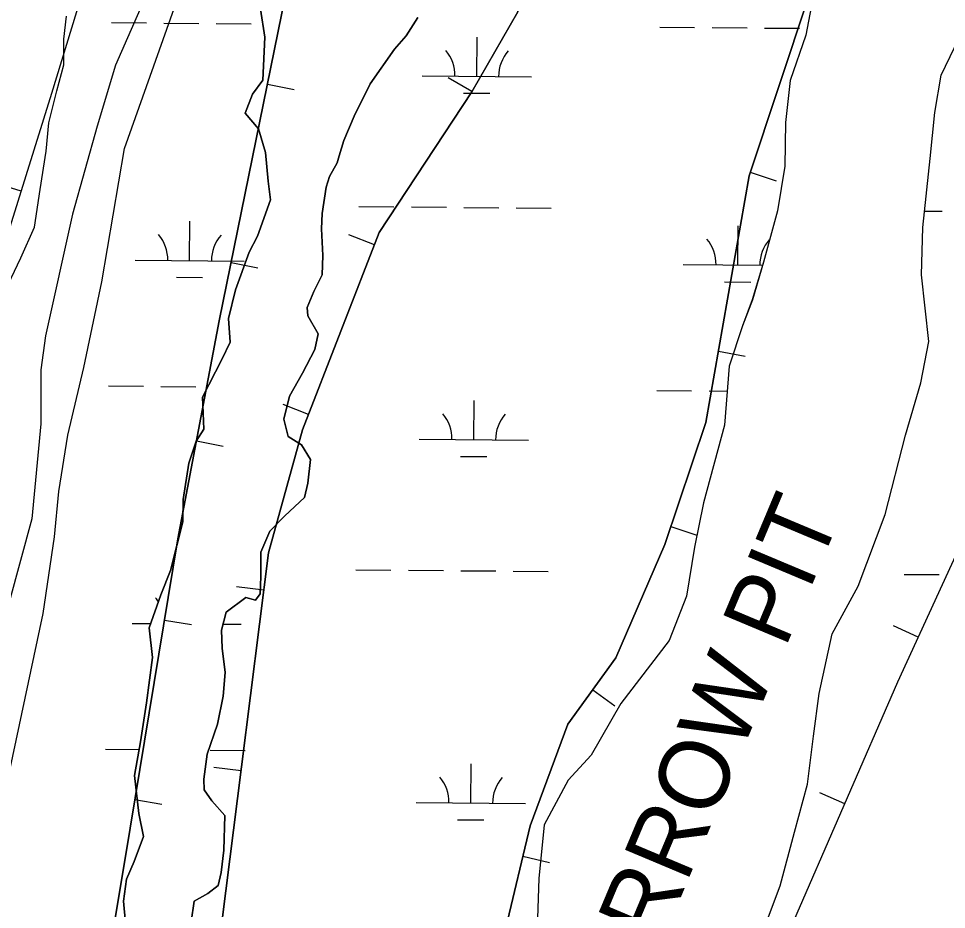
# Model space of a CAD drawing. Extents: x 3271442 to 3309282, y 752266 to 777610.
# Drawn here: x 3287641 to 3288490, y 773012 to 773828 of the extents above; entities that cross this region are included whole.
import ezdxf

# ---------------------------------------------------------------- set-up
doc = ezdxf.new("R2010")
doc.units = 0
for name, color, linetype in [('V-BORW-IDEN', 7, 'Continuous'), ('V-BORW-LINE', 7, 'Continuous'), ('V-SITE-VEGE', 7, 'Continuous'), ('V-TOPO-SHOR', 7, 'Continuous'), ('V-WETL-SWMP', 7, 'Continuous')]:
    doc.layers.add(name, color=color, linetype=linetype)

msp = doc.modelspace()

# ---------------------------------------------------------------- linework, layer by layer
at = {"layer": 'V-BORW-LINE'}
for p, q in [((3288056.11, 773761.26), (3288034.44, 773773.71)), ((3287868.85, 773768.1), (3287893.34, 773763.11)), ((3288310.88, 773687.36), (3288334.62, 773679.5)), ((3287643.36, 773669.95), (3287619.48, 773677.36)), ((3287966.74, 773620.96), (3287943.43, 773630)), ((3287835.59, 773604.85), (3287860.08, 773599.86)), ((3288281.68, 773523.38), (3288306.3, 773519.08)), ((3287906.5, 773465.63), (3287883.19, 773474.67)), ((3287803.8, 773441.32), (3287828.36, 773436.65)), ((3288238.19, 773363.04), (3288261.88, 773355.05)), ((3287865.43, 773304.59), (3287840.62, 773307.7)), ((3287774.59, 773277.31), (3287799.26, 773273.26)), ((3288464.55, 773261.51), (3288441.83, 773271.94)), ((3288166.6, 773213.49), (3288186.84, 773198.83)), ((3287844.66, 773139.29), (3287819.85, 773142.42)), ((3288397.31, 773109.09), (3288374.38, 773119.05)), ((3287747.62, 773112.91), (3287772.3, 773108.86)), ((3288102.7, 773061.24), (3288127.02, 773055.45))]:
    msp.add_line(p, q, dxfattribs=at)
for points in [[(3287960.94, 771424.94), (3288014.47, 771603.18), (3288066.68, 771823.14), (3288098.99, 772040.91), (3288128.22, 772249.7), (3288166.71, 772489.22), (3288222.94, 772713.67), (3288347.64, 772994.79), (3288445.81, 773220.69), (3288556.67, 773462.19), (3288616.39, 773637.62), (3288621.98, 773818.51), (3288618.9, 774004.11), (3288683.35, 774231.23), (3288776.13, 774650.85), (3288910.27, 775079.52), (3289045.78, 775496.93), (3289097.91, 775727.38), (3289093.15, 775796.21), (3289077.54, 775831.36)], [(3287946.02, 772379.82), (3287909.12, 772439.3), (3287896.09, 772502.81), (3287913.88, 772541.62), (3287925.45, 772619.81), (3287948.76, 772734.43), (3288021.53, 772853.96), (3288087.08, 772995.64), (3288109.28, 773088.9), (3288143.83, 773182.06), (3288187.85, 773242.85), (3288232.59, 773346.45), (3288270.29, 773458.26), (3288309.76, 773683.96), (3288364.37, 773848.74), (3288384.32, 773880.81), (3288422.6, 773916.87), (3288452.86, 774014.74), (3288459.7, 774112.63), (3288521, 774269.88)], [(3288521, 774269.88), (3288459.7, 774112.63), (3288452.86, 774014.74), (3288422.6, 773916.87), (3288384.32, 773880.81), (3288364.37, 773848.74), (3288309.76, 773683.96), (3288270.29, 773458.26), (3288232.59, 773346.45), (3288187.85, 773242.85), (3288143.83, 773182.06), (3288109.28, 773088.9), (3288087.08, 772995.64), (3288021.53, 772853.96), (3287948.76, 772734.43), (3287925.45, 772619.81), (3287913.88, 772541.62), (3287896.09, 772502.81), (3287909.12, 772439.3), (3287946.02, 772379.82)], [(3287874.44, 774249.61), (3287801.65, 774123.05), (3287726.03, 773939.09), (3287671.15, 773759.54), (3287624.33, 773608.59), (3287591.03, 773444.42), (3287559.74, 773238.91), (3287539.14, 773034.75), (3287545.26, 772863.66), (3287544.82, 772819.24), (3287514.6, 772720.21), (3287469.36, 772546.13), (3287459.15, 772437.07), (3287443.04, 772332.46)], [(3287885.48, 773849.72), (3287945.3, 773921.21), (3288015.71, 774031.69), (3288090.25, 774050.35), (3288124.87, 773978.23), (3288098.03, 773834.21), (3288055.98, 773761.02), (3287971.03, 773632.03), (3287900.96, 773451.34), (3287869.74, 773338.91), (3287845.1, 773142.82), (3287827.09, 773000.32), (3287812.48, 772836.24), (3287772.24, 772685.02), (3287706.68, 772579.32), (3287664.96, 772582.37), (3287662.79, 772664.89), (3287700.72, 772832.42), (3287739.07, 773060.74), (3287786.79, 773351.73), (3287824.7, 773551.43), (3287885.48, 773849.72)], [(3287885.48, 773849.72), (3287824.7, 773551.43), (3287786.79, 773351.73), (3287739.07, 773060.74), (3287700.72, 772832.42), (3287662.79, 772664.89), (3287664.96, 772582.37), (3287706.68, 772579.32), (3287772.24, 772685.02), (3287812.48, 772836.24), (3287827.09, 773000.32), (3287845.1, 773142.82), (3287869.74, 773338.91), (3287900.96, 773451.34), (3287971.03, 773632.03), (3288055.98, 773761.02), (3288098.03, 773834.21), (3288124.87, 773978.23), (3288090.25, 774050.35), (3288015.71, 774031.69), (3287944.3, 773945.08), (3287885.48, 773849.72)]]:
    msp.add_lwpolyline(points, dxfattribs=at)
at = {"layer": 'V-SITE-VEGE'}
for points in [[(3287630.5, 773128.36), (3287663.55, 773283.32), (3287673.87, 773353.57), (3287678, 773394.89), (3287686.27, 773446.54), (3287700.72, 773508.53), (3287717.24, 773587.04), (3287737.9, 773708.94), (3287793.66, 773865.96), (3287797.79, 773905.22), (3287812.25, 773940.34), (3287832.9, 773973.4), (3287863.88, 774029.19), (3287892.79, 774082.91), (3287923.77, 774120.1), (3287954.75, 774146.96), (3287993.99, 774163.49), (3288027.03, 774159.35), (3288066.27, 774144.89), (3288140.62, 774105.64), (3288188.12, 774082.91), (3288214.97, 774068.44), (3288243.01, 774030.1)], [(3287775.07, 773888.69), (3287729.63, 773785.39), (3287713.11, 773729.6), (3287690.4, 773649.02), (3287665.61, 773537.45), (3287661.48, 773506.46), (3287661.48, 773456.87), (3287653.22, 773370.1), (3287632.57, 773293.65)], [(3288367.66, 773845.12), (3288361.68, 773812.93), (3288347.46, 773771.39), (3288343.21, 773732.75), (3288342.48, 773692.93), (3288335.88, 773651.95), (3288322.81, 773605.14), (3288312.73, 773570.62), (3288303.85, 773546.64), (3288291.41, 773509.79), (3288287.1, 773455.91), (3288268.09, 773384.53), (3288259.73, 773344.15), (3288252.53, 773299.07), (3288236.57, 773258.72), (3288192.42, 773200.9), (3288165.29, 773153.56), (3288144.12, 773130.79), (3288122.29, 773089.87), (3288117.42, 773040.69), (3288116.11, 773004.38)], [(3287862.4, 773836.71), (3287866.41, 773810.92), (3287864.5, 773771.69), (3287855.08, 773758.84), (3287848.57, 773741.29), (3287860.81, 773727.18), (3287867.18, 773705.49), (3287869.42, 773679.12), (3287871.7, 773662.12), (3287859.85, 773628.78), (3287852.19, 773614.17), (3287839.75, 773579.66), (3287833.21, 773553.33), (3287834.89, 773531.65), (3287827.21, 773515.86), (3287809.51, 773481.37), (3287810.57, 773452.08), (3287803.5, 773440.98), (3287796.98, 773421.09), (3287791.58, 773387.72), (3287791.5, 773367.22), (3287780.2, 773322.75), (3287771.33, 773300.53), (3287760.67, 773270.11), (3287763.5, 773243.15), (3287758.07, 773201.59), (3287752.66, 773165.88), (3287747.27, 773134.86), (3287751.24, 773100.28), (3287755.26, 773079.18), (3287746.98, 773056.37), (3287739.89, 773039.99), (3287737.22, 773019.78)], [(3287628.39, 773578), (3287643.15, 773608.99), (3287655.55, 773637.06), (3287660.96, 773671.59), (3287666.36, 773706.72), (3287668.8, 773732.48), (3287675.94, 773761.74), (3287682.48, 773785.73), (3287682.56, 773809.16), (3287684.99, 773830.23)], [(3287985.27, 773799.93), (3287995.86, 773812.19), (3288006.47, 773829.13)], [(3287798.9, 773001.11), (3287801.89, 773019.84), (3287814.22, 773026.83), (3287823.62, 773034.41), (3287826.6, 773046.11), (3287829.02, 773066.6), (3287829.72, 773098.23), (3287818.06, 773111.74), (3287811.07, 773121.73), (3287810.52, 773131.69), (3287813.54, 773154.52), (3287823.01, 773182.01), (3287828.38, 773207.76), (3287830.22, 773229.43), (3287827.38, 773251.7), (3287826.86, 773268.1), (3287831.02, 773284.48), (3287849.23, 773297.89), (3287858, 773295.51), (3287862.12, 773301.35), (3287862.77, 773317.16), (3287862.85, 773339.42), (3287871.13, 773358.72), (3287884.65, 773372.72), (3287902.88, 773389.65), (3287905.85, 773402.52), (3287908.28, 773424.18), (3287900.13, 773437.69), (3287887.86, 773445.34), (3287883.82, 773461.17), (3287889.17, 773482.24), (3287900.97, 773503.28), (3287912.18, 773524.91), (3287915.16, 773539.54), (3287905.85, 773555.98), (3287905.29, 773563.6), (3287911.21, 773578.22), (3287918.88, 773593.42), (3287919.53, 773610.98), (3287918.45, 773635.59), (3287919.09, 773649.65), (3287922.7, 773673.65), (3287925.67, 773683.59), (3287932.74, 773695.87), (3287934.52, 773702.3), (3287938.68, 773716.34), (3287948.13, 773738.57), (3287962.89, 773768.38), (3287985.27, 773799.93)], [(3287737.22, 773019.78), (3287738.86, 773000.14)]]:
    msp.add_lwpolyline(points, dxfattribs=at)
at = {"layer": 'V-TOPO-SHOR'}
for points in [[(3288367.66, 773845.12), (3288361.68, 773812.93), (3288347.46, 773771.39), (3288343.21, 773732.75), (3288342.48, 773692.93), (3288335.88, 773651.95), (3288322.81, 773605.14), (3288312.73, 773570.62), (3288303.85, 773546.64), (3288291.41, 773509.79), (3288287.1, 773455.91), (3288268.09, 773384.53), (3288259.73, 773344.15), (3288252.53, 773299.07), (3288236.57, 773258.72), (3288192.42, 773200.9), (3288165.29, 773153.56), (3288144.12, 773130.79), (3288122.29, 773089.87), (3288117.42, 773040.69), (3288116.11, 773004.38)], [(3287737.21, 773019.78), (3287739.89, 773039.99), (3287746.98, 773056.37), (3287755.26, 773079.18), (3287751.24, 773100.28), (3287747.27, 773134.85), (3287752.66, 773165.88), (3287758.07, 773201.59), (3287763.5, 773243.15), (3287760.67, 773270.11), (3287771.33, 773300.53), (3287780.2, 773322.75), (3287791.5, 773367.22), (3287791.58, 773387.72), (3287796.98, 773421.09), (3287803.5, 773440.98), (3287810.57, 773452.08), (3287809.51, 773481.37), (3287827.21, 773515.86), (3287834.89, 773531.65), (3287833.21, 773553.33), (3287839.75, 773579.66), (3287852.19, 773614.17), (3287859.85, 773628.78), (3287871.7, 773662.12), (3287869.42, 773679.12), (3287867.18, 773705.49), (3287860.81, 773727.18), (3287848.57, 773741.29), (3287855.08, 773758.84), (3287864.5, 773771.69), (3287866.41, 773810.92), (3287862.4, 773836.71)], [(3288006.46, 773829.13), (3287995.86, 773812.19), (3287985.27, 773799.93), (3287962.89, 773768.38), (3287948.13, 773738.57), (3287938.68, 773716.34), (3287934.52, 773702.3), (3287932.74, 773695.87), (3287925.67, 773683.59), (3287922.7, 773673.65), (3287919.09, 773649.65), (3287918.45, 773635.59), (3287919.53, 773610.98), (3287918.88, 773593.42), (3287911.21, 773578.22), (3287905.29, 773563.6), (3287905.85, 773555.98), (3287915.16, 773539.54), (3287912.18, 773524.91), (3287900.97, 773503.28), (3287889.17, 773482.24), (3287883.82, 773461.17), (3287887.86, 773445.34), (3287900.13, 773437.68), (3287908.28, 773424.18), (3287905.85, 773402.52), (3287902.88, 773389.64), (3287884.65, 773372.72), (3287871.13, 773358.72), (3287862.85, 773339.42), (3287862.77, 773317.16), (3287862.12, 773301.35), (3287858, 773295.51), (3287849.23, 773297.89), (3287831.02, 773284.48), (3287826.85, 773268.1), (3287827.38, 773251.7), (3287830.22, 773229.43)], [(3287830.22, 773229.43), (3287828.38, 773207.76), (3287823.01, 773182.01), (3287813.54, 773154.52), (3287810.52, 773131.69), (3287811.07, 773121.73), (3287818.06, 773111.74), (3287829.72, 773098.23), (3287829.02, 773066.6), (3287826.6, 773046.11), (3287823.62, 773034.41), (3287814.22, 773026.83), (3287801.9, 773019.84), (3287798.9, 773001.11)], [(3287738.86, 773000.14), (3287737.21, 773019.78)]]:
    msp.add_lwpolyline(points, dxfattribs=at)
at = {"layer": 'V-WETL-SWMP'}
for p, q in [((3288367.66, 773845.12), (3288361.68, 773812.93)), ((3287862.4, 773836.71), (3287866.41, 773810.92)), ((3287682.57, 773809.16), (3287684.99, 773830.24)), ((3287726.02, 773824.33), (3287758.01, 773824.06)), ((3287774.01, 773823.93), (3287806.01, 773823.67)), ((3287822.01, 773823.54), (3287854.01, 773823.27)), ((3287995.86, 773812.19), (3288006.46, 773829.13)), ((3288485.71, 773776.14), (3288509.92, 773827.01)), ((3288227.91, 773820.19), (3288259.91, 773819.93)), ((3288275.9, 773819.8), (3288307.9, 773819.53)), ((3288323.9, 773819.4), (3288355.9, 773819.14)), ((3287682.48, 773785.73), (3287682.57, 773809.16)), ((3287866.41, 773810.92), (3287864.5, 773771.69)), ((3287985.27, 773799.93), (3287995.86, 773812.19)), ((3288060.47, 773775.14), (3288060.76, 773811.14)), ((3288361.68, 773812.93), (3288347.46, 773771.39)), ((3287962.89, 773768.38), (3287985.27, 773799.93)), ((3287675.94, 773761.74), (3287682.48, 773785.73)), ((3287864.5, 773771.69), (3287855.08, 773758.84)), ((3288010.47, 773775.55), (3288110.46, 773774.73)), ((3288479.72, 773742.19), (3288485.71, 773776.14)), ((3287948.13, 773738.57), (3287962.89, 773768.38)), ((3288347.46, 773771.39), (3288343.21, 773732.75)), ((3287668.8, 773732.48), (3287675.94, 773761.74)), ((3287855.08, 773758.84), (3287848.57, 773741.29)), ((3288048.34, 773759.81), (3288072.34, 773759.61)), ((3287848.57, 773741.29), (3287860.82, 773727.18)), ((3287938.68, 773716.34), (3287948.13, 773738.57)), ((3288475.46, 773700.03), (3288479.72, 773742.19)), ((3287666.36, 773706.72), (3287668.8, 773732.48)), ((3288343.21, 773732.75), (3288342.48, 773692.92)), ((3287860.82, 773727.18), (3287867.18, 773705.49)), ((3287934.52, 773702.3), (3287938.68, 773716.34)), ((3287660.96, 773671.6), (3287666.36, 773706.72)), ((3287867.18, 773705.49), (3287869.42, 773679.12)), ((3287925.67, 773683.59), (3287932.74, 773695.87)), ((3287932.74, 773695.87), (3287934.52, 773702.3)), ((3288468.78, 773636.8), (3288475.46, 773700.03)), ((3288342.48, 773692.92), (3288335.88, 773651.95)), ((3287869.42, 773679.12), (3287871.7, 773662.13)), ((3287922.7, 773673.65), (3287925.67, 773683.59)), ((3287655.55, 773637.06), (3287660.96, 773671.6)), ((3287919.09, 773649.65), (3287922.7, 773673.65)), ((3287871.7, 773662.13), (3287859.86, 773628.78)), ((3287952.64, 773655.95), (3287984.63, 773655.69)), ((3288000.63, 773655.56), (3288032.63, 773655.29)), ((3288048.63, 773655.16), (3288080.63, 773654.9)), ((3288096.63, 773654.77), (3288128.63, 773654.5)), ((3287918.45, 773635.59), (3287919.09, 773649.65)), ((3288335.88, 773651.95), (3288322.81, 773605.14)), ((3288470.35, 773651.69), (3288486.53, 773651.56)), ((3287643.15, 773608.99), (3287655.55, 773637.06)), ((3287797.63, 773606.49), (3287797.93, 773642.49)), ((3288299.52, 773602.35), (3288299.82, 773638.35)), ((3288467.44, 773593.46), (3288468.78, 773636.8)), ((3287859.86, 773628.78), (3287852.19, 773614.17)), ((3287919.53, 773610.98), (3287918.45, 773635.59)), ((3287852.19, 773614.17), (3287839.75, 773579.66)), ((3287918.88, 773593.42), (3287919.53, 773610.98)), ((3287628.39, 773578), (3287643.15, 773608.99)), ((3287747.63, 773606.9), (3287847.63, 773606.07)), ((3288249.52, 773602.76), (3288321.94, 773602.17)), ((3288322.81, 773605.14), (3288312.72, 773570.62)), ((3287911.21, 773578.22), (3287918.88, 773593.42)), ((3288474.24, 773532.52), (3288467.44, 773593.46)), ((3287785.5, 773591.15), (3287809.5, 773590.96)), ((3288287.4, 773587.02), (3288311.39, 773586.82)), ((3287839.75, 773579.66), (3287833.21, 773553.33)), ((3287905.29, 773563.6), (3287911.21, 773578.22)), ((3288312.72, 773570.62), (3288303.85, 773546.64)), ((3287905.85, 773555.98), (3287905.29, 773563.6)), ((3287833.21, 773553.33), (3287834.89, 773531.65)), ((3287915.16, 773539.54), (3287905.85, 773555.98)), ((3288303.85, 773546.64), (3288291.41, 773509.79)), ((3287912.18, 773524.91), (3287915.16, 773539.54)), ((3287834.89, 773531.65), (3287827.21, 773515.86)), ((3288467.07, 773494.47), (3288474.24, 773532.52)), ((3287900.97, 773503.28), (3287912.18, 773524.91)), ((3287827.21, 773515.86), (3287809.51, 773481.37)), ((3288291.41, 773509.79), (3288287.1, 773455.91)), ((3287889.17, 773482.24), (3287900.97, 773503.28)), ((3287723.28, 773491.66), (3287755.27, 773491.4)), ((3288452.83, 773446.5), (3288467.07, 773494.47)), ((3287771.27, 773491.27), (3287803.27, 773491)), ((3288225.17, 773487.53), (3288257.16, 773487.27)), ((3288273.16, 773487.13), (3288289.59, 773487)), ((3287809.51, 773481.37), (3287810.57, 773452.08)), ((3287883.82, 773461.17), (3287889.17, 773482.24)), ((3288057.73, 773442.48), (3288058.02, 773478.48)), ((3287887.86, 773445.34), (3287883.82, 773461.17)), ((3287810.57, 773452.08), (3287803.5, 773440.98)), ((3288287.1, 773455.91), (3288268.09, 773384.53)), ((3287803.5, 773440.98), (3287796.98, 773421.09)), ((3287900.13, 773437.68), (3287887.86, 773445.34)), ((3288007.73, 773442.89), (3288107.72, 773442.06)), ((3288434.39, 773373.94), (3288452.83, 773446.5)), ((3287908.28, 773424.18), (3287900.13, 773437.68)), ((3287905.85, 773402.52), (3287908.28, 773424.18)), ((3288045.6, 773427.14), (3288069.6, 773426.95)), ((3287796.98, 773421.09), (3287791.58, 773387.72)), ((3287902.88, 773389.64), (3287905.85, 773402.52)), ((3287884.65, 773372.73), (3287902.88, 773389.64)), ((3287791.58, 773387.72), (3287791.5, 773367.22)), ((3288268.09, 773384.53), (3288259.73, 773344.14)), ((3287871.13, 773358.72), (3287884.65, 773372.73)), ((3288409.54, 773308.43), (3288434.39, 773373.94)), ((3287791.5, 773367.22), (3287780.2, 773322.75)), ((3287862.86, 773339.42), (3287871.13, 773358.72)), ((3287862.77, 773317.16), (3287862.86, 773339.42)), ((3288259.73, 773344.14), (3288252.53, 773299.07)), ((3287780.2, 773322.75), (3287771.33, 773300.53)), ((3287949.9, 773323.29), (3287981.89, 773323.03)), ((3287997.89, 773322.89), (3288029.89, 773322.63)), ((3288045.89, 773322.5), (3288077.89, 773322.24)), ((3288093.89, 773322.1), (3288125.89, 773321.84)), ((3287862.12, 773301.35), (3287862.77, 773317.16)), ((3288451.79, 773319.16), (3288483.79, 773318.89)), ((3288385.95, 773264.59), (3288409.54, 773308.43)), ((3287771.33, 773300.53), (3287760.67, 773270.11)), ((3287831.02, 773284.48), (3287849.23, 773297.89)), ((3287849.23, 773297.89), (3287858, 773295.51)), ((3287858, 773295.51), (3287862.12, 773301.35)), ((3288252.53, 773299.07), (3288236.56, 773258.72)), ((3287826.85, 773268.1), (3287831.02, 773284.48)), ((3287744.89, 773274.23), (3287762.07, 773274.09)), ((3287828.24, 773273.55), (3287844.89, 773273.41)), ((3287760.67, 773270.11), (3287763.5, 773243.15)), ((3287827.38, 773251.7), (3287826.85, 773268.1)), ((3288374.03, 773210.16), (3288385.95, 773264.59)), ((3288236.56, 773258.72), (3288192.41, 773200.9)), ((3287830.22, 773229.43), (3287827.38, 773251.7)), ((3287763.5, 773243.15), (3287758.07, 773201.59)), ((3287828.38, 773207.76), (3287830.22, 773229.43)), ((3287823.01, 773182.01), (3287828.38, 773207.76)), ((3288368.61, 773170.94), (3288374.03, 773210.16)), ((3287758.07, 773201.59), (3287752.66, 773165.88)), ((3288192.41, 773200.9), (3288165.29, 773153.55)), ((3287813.54, 773154.52), (3287823.01, 773182.01)), ((3288363.17, 773127.03), (3288368.61, 773170.94)), ((3287752.66, 773165.88), (3287747.27, 773134.86)), ((3287720.54, 773159), (3287751.42, 773158.74)), ((3287810.52, 773131.69), (3287813.54, 773154.52)), ((3287816.53, 773158.21), (3287848.53, 773157.94)), ((3288165.29, 773153.55), (3288144.12, 773130.79)), ((3288054.99, 773109.81), (3288055.28, 773145.81)), ((3287747.27, 773134.86), (3287751.24, 773100.28)), ((3287811.07, 773121.73), (3287810.52, 773131.69)), ((3288144.12, 773130.79), (3288122.29, 773089.87)), ((3288351.29, 773083.15), (3288363.17, 773127.03)), ((3287818.06, 773111.74), (3287811.07, 773121.73)), ((3287829.72, 773098.23), (3287818.06, 773111.74)), ((3288004.99, 773110.22), (3288104.98, 773109.4)), ((3287751.24, 773100.28), (3287755.26, 773079.18)), ((3287829.02, 773066.6), (3287829.72, 773098.23)), ((3288042.86, 773094.48), (3288066.86, 773094.28)), ((3288122.29, 773089.87), (3288117.42, 773040.69)), ((3287755.26, 773079.18), (3287746.98, 773056.37)), ((3288338.21, 773033.99), (3288351.29, 773083.15)), ((3287826.6, 773046.11), (3287829.02, 773066.6)), ((3287746.98, 773056.37), (3287739.88, 773040)), ((3287823.62, 773034.41), (3287826.6, 773046.11)), ((3287739.88, 773040), (3287737.22, 773019.78)), ((3287814.22, 773026.83), (3287823.62, 773034.41)), ((3288117.42, 773040.69), (3288116.11, 773004.38)), ((3288325.79, 773000.65), (3288338.21, 773033.99)), ((3287801.9, 773019.84), (3287814.22, 773026.83)), ((3287737.22, 773019.78), (3287738.86, 773000.14)), ((3287798.9, 773001.11), (3287801.9, 773019.84))]:
    msp.add_line(p, q, dxfattribs=at)
for centre, start, end in [((3288005.23, 773776.07), 358.75626, 40.29991), ((3288115.71, 773775.16), 138.75625, 180.29991), ((3287742.39, 773607.42), 358.75626, 40.29991), ((3287852.88, 773606.51), 138.75625, 180.29991), ((3288244.29, 773603.28), 358.75626, 40.29991), ((3288354.77, 773602.37), 138.75625, 180.29991), ((3288002.49, 773443.41), 358.75626, 40.29991), ((3288112.97, 773442.5), 138.75625, 180.29991), ((3287739.65, 773274.75), 33.35916, 40.29991), ((3287999.75, 773110.74), 358.75626, 40.29991), ((3288110.23, 773109.83), 138.75625, 180.29991)]:
    msp.add_arc(centre, 35.25, start, end, dxfattribs=at)

# ---------------------------------------------------------------- texts
at = {"layer": 'V-BORW-IDEN'}
msp.add_text('BORROW PIT', height=64, rotation=67.21906, dxfattribs=at).set_placement((3288180.65, 772864.75))

doc.saveas('drawing.dxf')
